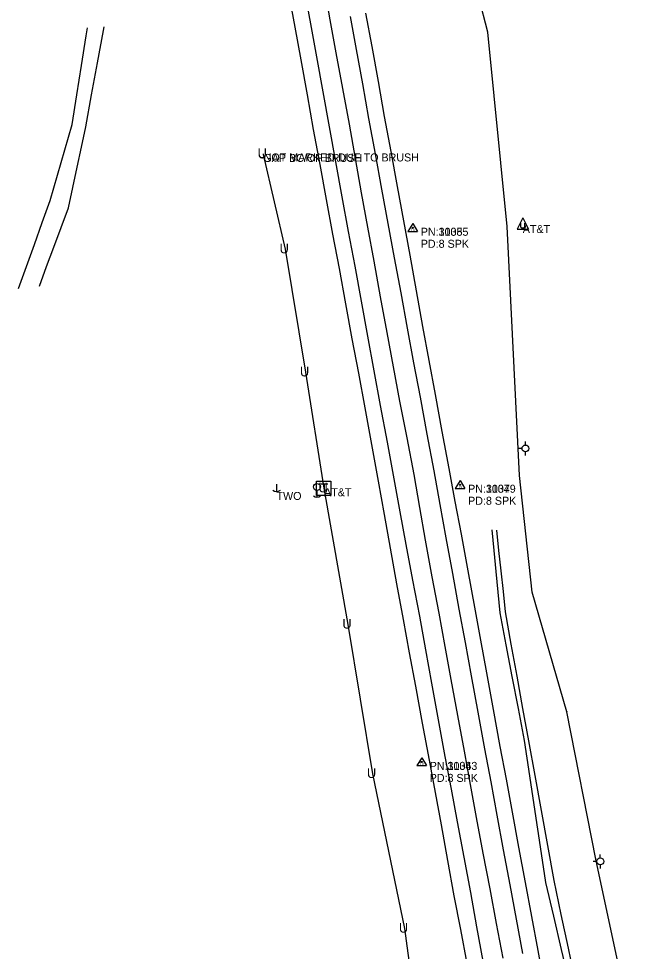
# Model space of a CAD drawing. Extents: x 954793 to 988390, y 1867850 to 1924428.
# Drawn here: x 986063 to 986442, y 1873361 to 1873944 of the extents above; entities that cross this region are included whole.
import ezdxf

# ---------------------------------------------------------------- set-up
doc = ezdxf.new("R2010")
doc.units = 0
for name, color, linetype in [('Default', 7, 'Continuous'), ('S_DITCHLINE', 7, 'Continuous'), ('S_DRIVEWAY', 7, 'Continuous'), ('S_EDGE_PAVEMENT', 7, 'Continuous'), ('S_FIBER_OPTIC_CABLE', 7, 'Continuous'), ('S_PAVEMENT_CROWN', 7, 'Continuous'), ('S_SECONDARY_CTL', 7, 'Continuous'), ('S_SECONDARY_CTL_ANNOT', 7, 'Continuous'), ('S_SHOULDER', 7, 'Continuous'), ('S_SURVEY_TEXT_ANNOT', 7, 'Continuous'), ('S_TELEPHONE_UTILITIES', 7, 'Continuous'), ('S_TELEPHONE_UTILITIES_ANNOT', 7, 'Continuous'), ('S_UNDERGROUND_CABLE', 7, 'Continuous'), ('S_UNDERGROUND_CABLE_ANNOT', 7, 'Continuous'), ('S_UTILITY_POLE', 7, 'Continuous'), ('S_UTILITY_POLE_ANNOT', 7, 'Continuous'), ('S_UTL_PT_SYM', 7, 'Continuous')]:
    doc.layers.add(name, color=color, linetype=linetype)

msp = doc.modelspace()

# ---------------------------------------------------------------- linework, layer by layer
at = {"layer": 'S_DITCHLINE'}
for points in [[(986435.42, 1873213.76), (986438.85, 1873215.8), (986432.77, 1873234), (986426.69, 1873252.2), (986422.99, 1873269.18), (986419.3, 1873286.16), (986415.6, 1873303.13), (986411.91, 1873320.11), (986406.97, 1873341.11), (986402.04, 1873362.11), (986397.11, 1873383.11), (986392.18, 1873404.11), (986388.86, 1873426.29), (986385.55, 1873448.47), (986382.24, 1873470.66), (986378.93, 1873492.84), (986375.09, 1873512.77), (986371.25, 1873532.7), (986367.41, 1873552.63), (986363.56, 1873572.56), (986362.36, 1873585.5), (986361.16, 1873598.44), (986359.96, 1873611.38), (986358.76, 1873624.32)], [(986410.78, 1873341.77), (986406.29, 1873362.93), (986401.8, 1873384.1), (986397.32, 1873405.27), (986393.36, 1873427.11), (986389.41, 1873448.96), (986385.46, 1873470.8), (986381.5, 1873492.64), (986377.88, 1873512.77), (986374.25, 1873532.91), (986370.62, 1873553.04), (986367, 1873573.17), (986365.64, 1873585.92), (986364.28, 1873598.67), (986362.93, 1873611.41), (986361.57, 1873624.16)]]:
    msp.add_lwpolyline(points, dxfattribs=at)
at = {"layer": 'S_DRIVEWAY'}
for points in [[(986063.01, 1873775.2), (986067.92, 1873788.92), (986072.84, 1873802.63), (986077.75, 1873816.35), (986082.67, 1873830.07), (986089.55, 1873853.85), (986096.44, 1873877.63), (986099.38, 1873896.06), (986102.32, 1873914.49), (986105.25, 1873932.92), (986106.05, 1873937.91)], [(986075.93, 1873776.52), (986080.48, 1873788.8), (986085.02, 1873801.08), (986089.57, 1873813.36), (986094.11, 1873825.64), (986096.81, 1873838.27), (986099.5, 1873850.9), (986102.19, 1873863.53), (986104.89, 1873876.17), (986108.56, 1873896.2), (986112.23, 1873916.24), (986115.91, 1873936.28), (986116.34, 1873938.64)]]:
    msp.add_lwpolyline(points, dxfattribs=at)
at = {"layer": 'S_EDGE_PAVEMENT'}
for points in [[(986352.97, 1873355), (986349.11, 1873376.37), (986345.25, 1873397.74), (986341.1, 1873419.89), (986336.95, 1873442.04), (986333.18, 1873462.41), (986329.42, 1873482.79), (986325.25, 1873505.68), (986321.07, 1873528.57), (986317.24, 1873549.51), (986313.41, 1873570.45), (986309.17, 1873592.88), (986304.93, 1873615.3), (986301.19, 1873635.72), (986297.45, 1873656.14), (986293.22, 1873679.08), (986289, 1873702.03), (986285, 1873723.7), (986281.01, 1873745.36), (986277.04, 1873767.19), (986273.08, 1873789.03), (986269.03, 1873810.75), (986264.98, 1873832.47), (986261.02, 1873854.27), (986257.06, 1873876.06), (986253.1, 1873897.96), (986249.13, 1873919.85), (986245.4, 1873940.43), (986241.68, 1873961)], [(986377.89, 1873359.75), (986373.87, 1873381.17), (986369.85, 1873402.59), (986365.84, 1873424.39), (986361.82, 1873446.19), (986357.99, 1873466.9), (986354.16, 1873487.61), (986350.01, 1873510.4), (986345.85, 1873533.19), (986341.98, 1873554.01), (986338.11, 1873574.84), (986334.05, 1873597.08), (986329.99, 1873619.32), (986326.18, 1873640.29), (986322.38, 1873661.27), (986318.11, 1873684.25), (986313.83, 1873707.24), (986309.83, 1873728.78), (986305.82, 1873750.33), (986301.76, 1873772.36), (986297.7, 1873794.4), (986293.76, 1873815.83), (986289.82, 1873837.25), (986285.77, 1873859.35), (986281.72, 1873881.45), (986277.85, 1873902.93), (986273.98, 1873924.41), (986270.2, 1873945.07)]]:
    msp.add_lwpolyline(points, dxfattribs=at)
at = {"layer": 'S_FIBER_OPTIC_CABLE'}
for p, q in [((986355.96, 1873935.35), (986326.58, 1874047.4)), ((986368.08, 1873813.86), (986355.96, 1873935.35)), ((986375.76, 1873658.37), (986368.08, 1873813.86)), ((986383.7, 1873585.41), (986375.76, 1873658.37)), ((986405.26, 1873510.77), (986383.7, 1873585.41)), ((986423.35, 1873418.7), (986405.26, 1873510.77)), ((986442.44, 1873329.92), (986423.35, 1873418.7))]:
    msp.add_line(p, q, dxfattribs=at)
at = {"layer": 'S_PAVEMENT_CROWN'}
msp.add_lwpolyline([(986365.43, 1873356.75), (986361.38, 1873378.41), (986357.32, 1873400.07), (986353.12, 1873422.36), (986348.93, 1873444.65), (986345.16, 1873465.37), (986341.39, 1873486.1), (986337.24, 1873508.46), (986333.08, 1873530.82), (986329.32, 1873551.57), (986325.56, 1873572.32), (986321.3, 1873595.07), (986317.03, 1873617.82), (986313.46, 1873638.41), (986309.88, 1873659.01), (986305.5, 1873681.88), (986301.11, 1873704.75), (986297.11, 1873726.25), (986293.11, 1873747.75), (986289.02, 1873769.97), (986284.92, 1873792.2), (986281.05, 1873813.52), (986277.18, 1873834.84), (986273.35, 1873856.34), (986269.51, 1873877.84), (986265.34, 1873900.09), (986261.17, 1873922.34), (986257.53, 1873942.95), (986253.9, 1873963.56)], dxfattribs=at)
at = {"layer": 'S_SECONDARY_CTL'}
for p, q in [((986309.09, 1873815.71), (986306.08, 1873810.76)), ((986309.09, 1873815.71), (986312.04, 1873810.76)), ((986306.08, 1873810.76), (986312.04, 1873810.76)), ((986338.63, 1873655.16), (986335.62, 1873650.2)), ((986338.63, 1873655.16), (986341.58, 1873650.2)), ((986335.62, 1873650.2), (986341.58, 1873650.2)), ((986314.65, 1873482.01), (986311.64, 1873477.05)), ((986314.65, 1873482.01), (986317.6, 1873477.05)), ((986311.64, 1873477.05), (986317.6, 1873477.05))]:
    msp.add_line(p, q, dxfattribs=at)
for centre, radius in [((986309.09, 1873813.1), 0.311), ((986309.09, 1873813.1), 0.183), ((986309.09, 1873813.1), 0.103), ((986338.63, 1873652.55), 0.311), ((986338.63, 1873652.55), 0.183), ((986338.63, 1873652.55), 0.103), ((986314.65, 1873479.4), 0.311), ((986314.65, 1873479.4), 0.183), ((986314.65, 1873479.4), 0.103)]:
    msp.add_circle(centre, radius, dxfattribs=at)
at = {"layer": 'S_SHOULDER'}
for points in [[(986343.09, 1873353.54), (986339.03, 1873374.66), (986334.96, 1873395.78), (986330.95, 1873417.89), (986326.94, 1873440), (986323.19, 1873460.25), (986319.44, 1873480.5), (986315.23, 1873503.58), (986311.03, 1873526.67), (986307.12, 1873547.46), (986303.2, 1873568.26), (986299.2, 1873590.64), (986295.19, 1873613.01), (986291.45, 1873633.89), (986287.7, 1873654.77), (986283.52, 1873677.72), (986279.34, 1873700.66), (986275.32, 1873722.21), (986271.3, 1873743.75), (986267.3, 1873765.67), (986263.29, 1873787.59), (986259.28, 1873809.14), (986255.27, 1873830.7), (986251.22, 1873852.6), (986247.18, 1873874.49), (986243.32, 1873896.23), (986239.47, 1873917.96), (986235.71, 1873938.41), (986231.95, 1873958.85)], [(986391.54, 1873338.85), (986387.42, 1873361.49), (986383.43, 1873382.79), (986379.45, 1873404.08), (986375.4, 1873426.05), (986371.35, 1873448.03), (986367.53, 1873468.56), (986363.72, 1873489.09), (986359.55, 1873512.08), (986355.38, 1873535.08), (986351.58, 1873555.55), (986347.77, 1873576.02), (986343.6, 1873598.84), (986339.42, 1873621.65), (986335.63, 1873642.13), (986331.83, 1873662.6), (986327.54, 1873685.76), (986323.24, 1873708.92), (986319.32, 1873730.17), (986315.4, 1873751.41), (986311.39, 1873773.68), (986307.39, 1873795.94), (986303.46, 1873817.43), (986299.53, 1873838.91), (986295.53, 1873860.82), (986291.53, 1873882.72), (986287.61, 1873904.53), (986283.68, 1873926.35), (986279.85, 1873947.2)]]:
    msp.add_lwpolyline(points, dxfattribs=at)
at = {"layer": 'S_TELEPHONE_UTILITIES'}
msp.add_lwpolyline([(986248.98, 1873645.85), (986248.98, 1873654.85), (986257.98, 1873654.85), (986257.98, 1873645.85)], close=True, dxfattribs=at)
at = {"layer": 'S_UNDERGROUND_CABLE'}
for p, q in [((986215.84, 1873858.96), (986215.83, 1873859.23)), ((986229.54, 1873799.66), (986215.84, 1873858.96)), ((986377.77, 1873819.39), (986374.25, 1873812.3)), ((986376.57, 1873813.54), (986376.57, 1873815.98)), ((986377.77, 1873819.39), (986381.26, 1873812.3)), ((986378.94, 1873815.98), (986378.94, 1873813.54)), ((986374.25, 1873812.3), (986381.26, 1873812.3)), ((986377.19, 1873812.88), (986376.57, 1873813.54)), ((986378.39, 1873812.88), (986377.19, 1873812.88)), ((986378.94, 1873813.54), (986378.39, 1873812.88)), ((986242.25, 1873722.79), (986229.54, 1873799.66)), ((986253.82, 1873650.35), (986242.25, 1873722.79)), ((986268.74, 1873565.27), (986253.82, 1873650.35)), ((986284.09, 1873471.93), (986268.74, 1873565.27)), ((986304.04, 1873375.26), (986284.09, 1873471.93)), ((986312.84, 1873311.49), (986304.04, 1873375.26))]:
    msp.add_line(p, q, dxfattribs=at)
at = {"layer": 'S_UTILITY_POLE'}
for p, q in [((986379.45, 1873677.32), (986379.45, 1873679.57)), ((986377.36, 1873675.19), (986375.03, 1873675.19)), ((986379.53, 1873670.77), (986379.53, 1873673.09)), ((986223.99, 1873652.99), (986223.99, 1873648.27)), ((986249.26, 1873648.99), (986249.26, 1873644.76)), ((986426.2, 1873419.35), (986426.2, 1873421.6)), ((986424.11, 1873417.22), (986421.78, 1873417.22)), ((986426.28, 1873412.8), (986426.28, 1873415.13))]:
    msp.add_line(p, q, dxfattribs=at)
for centre in [(986379.45, 1873675.21), (986249.26, 1873651.17), (986426.2, 1873417.24)]:
    msp.add_circle(centre, 2.13, dxfattribs=at)
for centre, radius in [((986224.05, 1873651.69), 3.41), ((986249.26, 1873647.87), 3.09)]:
    msp.add_arc(centre, radius, 226.39718, 313.60282, dxfattribs=at)
at = {"layer": 'S_UTL_PT_SYM'}
for points in [[(986355.96, 1873935.35), (986355.96, 1873935.4), (986355.96, 1873935.35), (986355.91, 1873935.35), (986355.96, 1873935.35), (986355.96, 1873935.3), (986355.96, 1873935.35), (986356.01, 1873935.35)], [(986368.08, 1873813.86), (986368.08, 1873813.91), (986368.08, 1873813.86), (986368.03, 1873813.86), (986368.08, 1873813.86), (986368.08, 1873813.81), (986368.08, 1873813.86), (986368.13, 1873813.86)], [(986375.76, 1873658.37), (986375.76, 1873658.42), (986375.76, 1873658.37), (986375.71, 1873658.37), (986375.76, 1873658.37), (986375.76, 1873658.32), (986375.76, 1873658.37), (986375.81, 1873658.37)], [(986383.7, 1873585.41), (986383.7, 1873585.46), (986383.7, 1873585.41), (986383.65, 1873585.41), (986383.7, 1873585.41), (986383.7, 1873585.36), (986383.7, 1873585.41), (986383.75, 1873585.41)], [(986405.26, 1873510.77), (986405.26, 1873510.82), (986405.26, 1873510.77), (986405.21, 1873510.77), (986405.26, 1873510.77), (986405.26, 1873510.72), (986405.26, 1873510.77), (986405.31, 1873510.77)], [(986423.35, 1873418.7), (986423.35, 1873418.75), (986423.35, 1873418.7), (986423.3, 1873418.7), (986423.35, 1873418.7), (986423.35, 1873418.65), (986423.35, 1873418.7), (986423.4, 1873418.7)]]:
    msp.add_lwpolyline(points, dxfattribs=at)

# ---------------------------------------------------------------- texts
at = {"layer": 'Default'}
for p in [(986212.2, 1873856.69), (986212.21, 1873856.42), (986225.91, 1873797.11), (986238.62, 1873720.24), (986250.19, 1873647.8), (986265.11, 1873562.72), (986280.46, 1873469.38), (986300.41, 1873372.71)]:
    msp.add_text('U', height=6, rotation=360, dxfattribs=at).set_placement(p)
at = {"layer": 'S_SECONDARY_CTL'}
for p in [(986307.88, 1873811.09), (986337.43, 1873650.54), (986313.45, 1873477.38)]:
    msp.add_text('TV', height=1.5, rotation=360, dxfattribs=at).set_placement(p)
at = {"layer": 'S_SECONDARY_CTL_ANNOT'}
for s, p in [('PN:1138', (986314.09, 1873808.1)), ('PN:30055', (986314.09, 1873808.1)), ('PD:8 SPK', (986314.09, 1873800.6)), ('PD:8 SPK', (986314.09, 1873800.6)), ('PN:1137', (986343.63, 1873647.55)), ('PN:30049', (986343.63, 1873647.55)), ('PD:8 SPK', (986343.63, 1873640.05)), ('PD:8 SPK', (986343.63, 1873640.05)), ('PN:1136', (986319.65, 1873474.4)), ('PN:30043', (986319.65, 1873474.4)), ('PD:8 SPK', (986319.65, 1873466.9)), ('PD:8 SPK', (986319.65, 1873466.9))]:
    msp.add_text(s, height=5, dxfattribs=at).set_placement(p)
at = {"layer": 'S_SURVEY_TEXT_ANNOT'}
msp.add_text('NOT MARKED DUE TO BRUSH', height=5, dxfattribs=at).set_placement((986215.99, 1873854.54))
at = {"layer": 'S_TELEPHONE_UTILITIES'}
msp.add_text('T', height=6, rotation=360, dxfattribs=at).set_placement((986251.54, 1873647.35))
at = {"layer": 'S_TELEPHONE_UTILITIES_ANNOT'}
msp.add_text('AT&T', height=5, dxfattribs=at).set_placement((986253.71, 1873645.36))
at = {"layer": 'S_UNDERGROUND_CABLE_ANNOT'}
msp.add_text('GAP BC/OF BRUSH', height=5, dxfattribs=at).set_placement((986215.83, 1873854.23))
at = {"layer": 'S_UTILITY_POLE_ANNOT'}
for s, p in [('AT&T', (986377.77, 1873809.85)), ('TWO', (986224.01, 1873643.05))]:
    msp.add_text(s, height=5, dxfattribs=at).set_placement(p)

doc.saveas('drawing.dxf')
